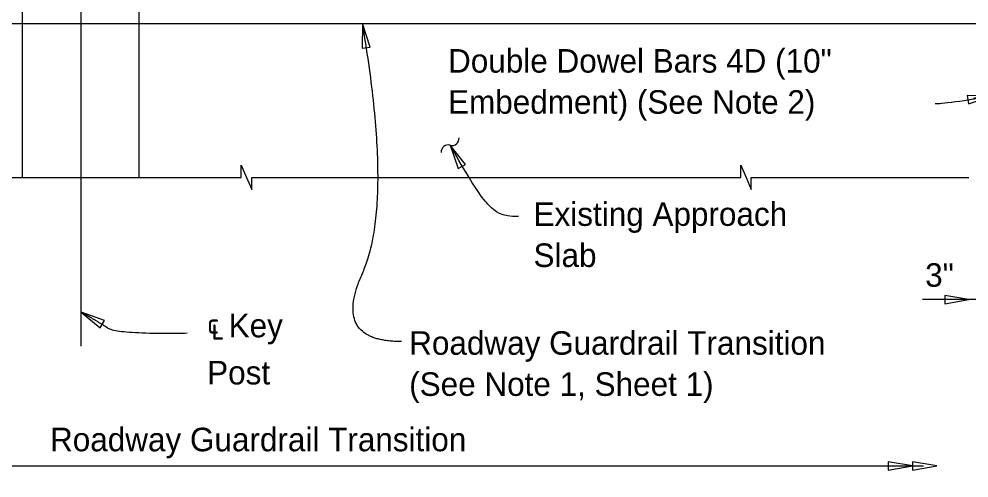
# Model space of a CAD drawing. Extents: x 21526.6 to 21595.9, y 56114.9 to 56157.2.
# Drawn here: x 21554.27 to 21562.41, y 56142.68 to 56146.61 of the extents above; entities that cross this region are included whole.
import ezdxf

# ---------------------------------------------------------------- set-up
doc = ezdxf.new("R2010")
doc.units = 0
for name, color, linetype in [('AdhocPoint_dp', 7, 'Continuous'), ('Border', 7, 'Continuous'), ('Patterning', 7, 'Continuous'), ('PlotBorder_dp', 7, 'Continuous')]:
    doc.layers.add(name, color=color, linetype=linetype)

msp = doc.modelspace()

# ---------------------------------------------------------------- linework, layer by layer
at = {"layer": 'AdhocPoint_dp'}
for p, q in [((21554.3018, 56145.2536), (21554.3018, 56149.7195)), ((21555.3018, 56145.2536), (21555.3018, 56147.2315))]:
    msp.add_line(p, q, dxfattribs=at)
at = {"layer": 'Patterning'}
msp.add_line((21552.8484, 56146.5703), (21566.2337, 56146.5703), dxfattribs=at)
at = {"layer": 'PlotBorder_dp'}
for p, q in [((21554.8018, 56147.4803), (21554.8018, 56143.8094)), ((21565.892, 56144.2072), (21562.0129, 56144.2072))]:
    msp.add_line(p, q, dxfattribs=at)
for points in [[(21557.2163, 56146.5703), (21557.2118, 56146.3591), (21557.2816, 56146.3694)], [(21562.6076, 56145.9501), (21562.3964, 56145.9541), (21562.4069, 56145.8843)], [(21557.9664, 56145.529), (21558.0368, 56145.3299), (21558.0985, 56145.3642)], [(21562.4118, 56144.2072), (21562.2036, 56144.2425), (21562.2036, 56144.1719)], [(21554.8059, 56144.0994), (21554.9698, 56143.9662), (21555.0045, 56144.0276)], [(21561.9289, 56142.7836), (21561.7207, 56142.8189), (21561.7207, 56142.7483)], [(21562.1372, 56142.7836), (21561.9289, 56142.8189), (21561.9289, 56142.7483)]]:
    msp.add_lwpolyline(points, close=True, dxfattribs=at)
for points in [[(21554.1818, 56145.2536), (21556.1773, 56145.2536), (21556.1773, 56145.3569), (21556.2223, 56145.2536), (21556.2673, 56145.1503), (21556.2673, 56145.2536), (21558.1321, 56145.2536)], [(21558.1321, 56145.2536), (21560.457, 56145.2536), (21560.457, 56145.3569), (21560.502, 56145.2536), (21560.547, 56145.1503), (21560.547, 56145.2536), (21562.4118, 56145.2536)], [(21546.0419, 56142.7836), (21549.8888, 56142.7836), (21549.8888, 56142.8869), (21549.9338, 56142.7836), (21549.9788, 56142.6803), (21549.9788, 56142.7836), (21562.0226, 56142.7836)]]:
    msp.add_lwpolyline(points, dxfattribs=at)
for centre, start, end in [((21557.9833, 56145.5862), 253.27971, 5.00693), ((21557.949, 56145.472), 73.27971, 185.00693)]:
    msp.add_arc(centre, 0.0596, start, end, dxfattribs=at)
for points, degree in [([(21557.549, 56143.8481), (21556.951, 56143.8481), (21557.4814, 56145.0202), (21557.2162, 56146.5703)], 2), ([(21562.1224, 56145.8852), (21562.1271, 56145.8853), (21562.2209, 56145.8879), (21562.6076, 56145.9501), (21562.2488, 56145.9047), (21563.2593, 56146.015), (21564.981, 56146.272)], 3), ([(21558.5511, 56144.9177), (21558.4027, 56144.9177), (21558.3055, 56144.997), (21558.1845, 56145.1464), (21557.9664, 56145.529)], 3), ([(21555.7124, 56143.9187), (21555.117, 56143.9087), (21554.9598, 56144.0124), (21554.8059, 56144.0994)], 2)]:
    msp.add_open_spline(points, degree=degree, dxfattribs=at)

# ---------------------------------------------------------------- texts
at = {"layer": 'Border'}
for s, p in [('3"', (21562.0364, 56144.317)), ('℄ Key ', (21555.8849, 56143.8844)), ('Post', (21555.8849, 56143.4812))]:
    msp.add_text(s, height=0.2016, dxfattribs=at).set_placement(p)
at = {"layer": 'PlotBorder_dp'}
for s, p in [('Double Dowel Bars 4D (10"', (21557.9488, 56146.1504)), ('Embedment) (See Note 2)', (21557.9488, 56145.7984)), ('Existing Approach ', (21558.6812, 56144.8385)), ('Slab', (21558.6812, 56144.4865)), ('Roadway Guardrail Transition', (21557.6159, 56143.7351)), ('(See Note 1, Sheet 1)', (21557.6159, 56143.3831)), ('Roadway Guardrail Transition', (21554.539, 56142.909))]:
    msp.add_text(s, height=0.2016, dxfattribs=at).set_placement(p)

doc.saveas('drawing.dxf')
